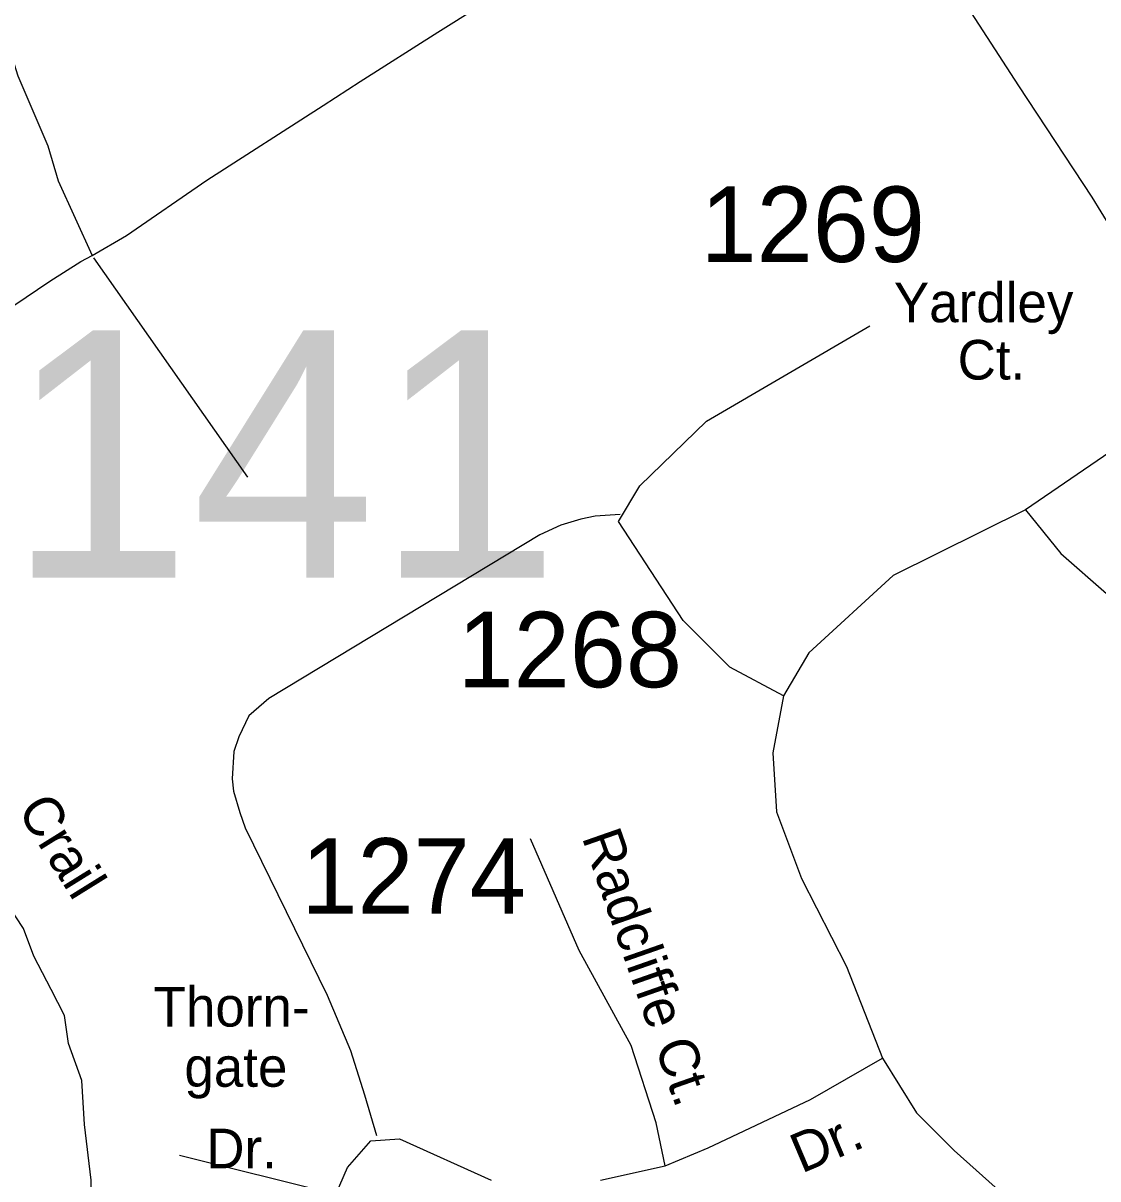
# Model space of a CAD drawing. Extents: x 884530 to 1028605, y 526725 to 653634.
# Drawn here: x 962593 to 964374, y 576515 to 578430 of the extents above; entities that cross this region are included whole.
import ezdxf

# ---------------------------------------------------------------- set-up
doc = ezdxf.new("R2010")
doc.units = 0
for name, color, linetype in [('Exist Road Non-System Type 51', 7, 'Continuous'), ('Exist Road Non-System Type 51 Label', 7, 'Continuous'), ('Exist Road Secondary Structure Standard Bridge Number Label', 7, 'Continuous'), ('Exist Road Secondary Type 41 Attributed', 7, 'Continuous'), ('Exist Road Secondary Type 51 Attributed', 7, 'Continuous'), ('Exist Road Secondary Type 51 Label', 7, 'Continuous'), ('Exist Road Secondary Type 51 Number Label', 7, 'Continuous')]:
    doc.layers.add(name, color=color, linetype=linetype)

msp = doc.modelspace()

# ---------------------------------------------------------------- linework, layer by layer
at = {"layer": 'Exist Road Non-System Type 51'}
for p, q in [((962709.9, 578040.7), (962965.4, 577677.3)), ((963111.8, 576489.3), (962852.6, 576553.6))]:
    msp.add_line(p, q, dxfattribs=at)
msp.add_lwpolyline([(963582.5, 577615.6), (963541.2, 577613.1), (963517.2, 577607.7), (963484.1, 577598.2), (963449.7, 577582.2), (963000.4, 577310.6), (962967.2, 577282), (962950.7, 577247.3), (962942.5, 577223.3), (962939.7, 577177.9), (962942, 577157.4), (962952.2, 577122.1), (962961.4, 577096.9), (963096.9, 576819.3), (963135.6, 576727.7), (963158.9, 576654.2), (963179, 576587.2)], dxfattribs=at)
at = {"layer": 'Exist Road Secondary Type 41 Attributed'}
for points in [[(962028.1, 578909.6), (962092.4, 578928.9), (962134.9, 578943.5), (962173.7, 578959.9), (962202.8, 578959.9), (962243.4, 578950.1), (962271.4, 578947.2), (962299.5, 578936.3), (962338.9, 578914.9), (962369.9, 578883.1), (962405.7, 578794), (962455.9, 578694.6), (962492.8, 578607.7), (962547.1, 578459.8), (962584.6, 578342.2), (962634.5, 578226.3), (962651.4, 578168.5), (962707.9, 578044.6)], [(962567.8, 575979.3), (962595.2, 576076.6), (962630.9, 576183.3), (962635.4, 576197.2), (962661.7, 576260.3), (962695, 576357.3), (962701.5, 576431.5), (962705.9, 576479.9), (962706.4, 576512.8), (962694.9, 576605.3), (962690.5, 576677.9), (962668.5, 576739.6), (962662, 576785.8), (962640, 576828.9), (962611.4, 576883.9), (962593.8, 576930.1), (962554.3, 576989.5)]]:
    msp.add_lwpolyline(points, dxfattribs=at)
at = {"layer": 'Exist Road Secondary Type 51 Attributed'}
for points in [[(963930.3, 578822.7), (964046.3, 578629.3), (964242.5, 578325.8), (964364.4, 578141.3), (964453.7, 577995.5), (964468.5, 577900.2), (964444.7, 577808), (964394.2, 577718.7), (964254.4, 577623.5)], [(962707.9, 578044.6), (962764.7, 578078), (962897.8, 578169.5), (963090.3, 578292.9), (963151.7, 578332.9), (963280.6, 578414.5), (963348.4, 578457.1)], [(962416.8, 577864.1), (962497.2, 577907.6), (962637.9, 578002.3), (962689, 578034.7), (962707.9, 578044.6)], [(963579.9, 577603.9), (963615.5, 577663.4), (963725.6, 577770.5), (963996.2, 577928.2)], [(964254.4, 577623.5), (964034.8, 577514.6), (963895.1, 577386.6), (963853.4, 577315.2)], [(964254.4, 577623.5), (964312.6, 577551), (964388.3, 577484.7), (964546.1, 577402.6), (964628.1, 577358.4)], [(963853.4, 577315.2), (963764.2, 577362.8), (963686.9, 577440.2), (963579.9, 577603.9)], [(963853.4, 577315.2), (963835.7, 577221.1), (963841.6, 577122.9), (963883.3, 577012.8), (963957.6, 576866.9), (964017.1, 576715.2)], [(963657.3, 576536.6), (963642.4, 576608), (963600.8, 576736), (963514.5, 576893.7), (963434.2, 577078.2)], [(963657.3, 576536.6), (963728.6, 576566.4), (963898.1, 576646.7), (964017.1, 576715.2)], [(964017.1, 576715.2), (964073.5, 576624.4), (964135.9, 576561.9), (964219.2, 576487.5), (964317.3, 576431), (964430.3, 576383.4), (964504.7, 576311.9), (964552.3, 576234.6), (964573.1, 576115.5), (964576.1, 575948.9), (964582, 575886.4), (964543.4, 575823.9), (964466, 575728.7), (964418.5, 575639.4), (964388.7, 575544.2), (964364.9, 575483.4)], [(963089.3, 576438.4), (963130.9, 576533.7), (963169.6, 576578.3), (963217.1, 576581.3), (963368.8, 576512.8)], [(963550.2, 576512.8), (963657.3, 576536.6)]]:
    msp.add_lwpolyline(points, dxfattribs=at)

# ---------------------------------------------------------------- texts
at = {"layer": 'Exist Road Non-System Type 51 Label'}
for s, p in [('Thorn-', (962809.5, 576767.5)), ('gate', (962860.6, 576667.7)), ('Dr.', (962896.8, 576532.7))]:
    msp.add_text(s, height=65.62, dxfattribs=at).set_placement(p)
at = {"layer": 'Exist Road Secondary Structure Standard Bridge Number Label'}
msp.add_text('141', height=410.1, dxfattribs=at).set_placement((962567.5, 577510.9))
at = {"layer": 'Exist Road Secondary Type 51 Label'}
for s, p in [('Yardley ', (964036.1, 577934.1)), ('Ct.', (964141.8, 577839.2))]:
    msp.add_text(s, height=65.62, dxfattribs=at).set_placement(p)
for s, height, rotation, p in [('Crail', 65.62, 301.8298, (962582.7, 577126.4)), ('Radcliffe Ct.', 65.617, 289.2666, (963518.6, 577081.2)), ('Dr.', 65.62, 22.9815, (963883.2, 576523.6))]:
    msp.add_text(s, height=height, rotation=rotation, dxfattribs=at).set_placement(p)
at = {"layer": 'Exist Road Secondary Type 51 Number Label'}
for s, p in [('1269', (963715.8, 578034)), ('1268', (963313.2, 577329.5)), ('1274', (963054.5, 576954.4))]:
    msp.add_text(s, height=125, dxfattribs=at).set_placement(p)

doc.saveas('drawing.dxf')
